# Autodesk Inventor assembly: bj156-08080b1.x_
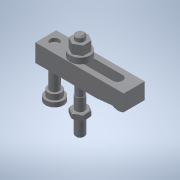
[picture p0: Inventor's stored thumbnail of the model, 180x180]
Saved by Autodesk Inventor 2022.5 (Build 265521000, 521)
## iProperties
Part Number: bj156-08080b1.x_
Material: 一般
Document SubType Name: Assembly
Designer: ImaoCorp
Sending System: SOLIDWORKS 2017-2017317
MC: AMD64
MC_MODEL: Intel64 Family 6 Model 60 Stepping 3, GenuineIntel
OS: Windows_NT
FRU: Parasolid Version 29.0, build 201,  4-17-2017
FORMAT: text
GUISE: transmit
KEY: bj156-08080b1
FILE: bj156-08080b1.x_t
DATE: Fri Mar 15 10:21:38 2019
Author: ImaoCorp
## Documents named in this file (6)
- X:\14_SW2022-Inv2022\00_全2023-1023新製品(TCC)まで\b\bj156-08080b1\BJ156-08080B1.iam
- X:\14_SW2022-Inv2022\00_全2023-1023新製品(TCC)まで\b\bj156-08080b1\bj156-08080b1_01.ipt
- X:\14_SW2022-Inv2022\00_全2023-1023新製品(TCC)まで\b\bj156-08080b1\bj156-08080b1_02.ipt
- X:\14_SW2022-Inv2022\00_全2023-1023新製品(TCC)まで\b\bj156-08080b1\bj156-08080b1_03.ipt
- X:\14_SW2022-Inv2022\00_全2023-1023新製品(TCC)まで\b\bj156-08080b1\bj156-08080b1_04.ipt
- X:\14_SW2022-Inv2022\00_全2023-1023新製品(TCC)まで\b\bj156-08080b1\bj156-08080b1_05.ipt
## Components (5 placed, 5 different names)
1. bj156-08080b1_01
2. bj156-08080b1_02
3. bj156-08080b1_03
4. bj156-08080b1_04
5. bj156-08080b1_05
